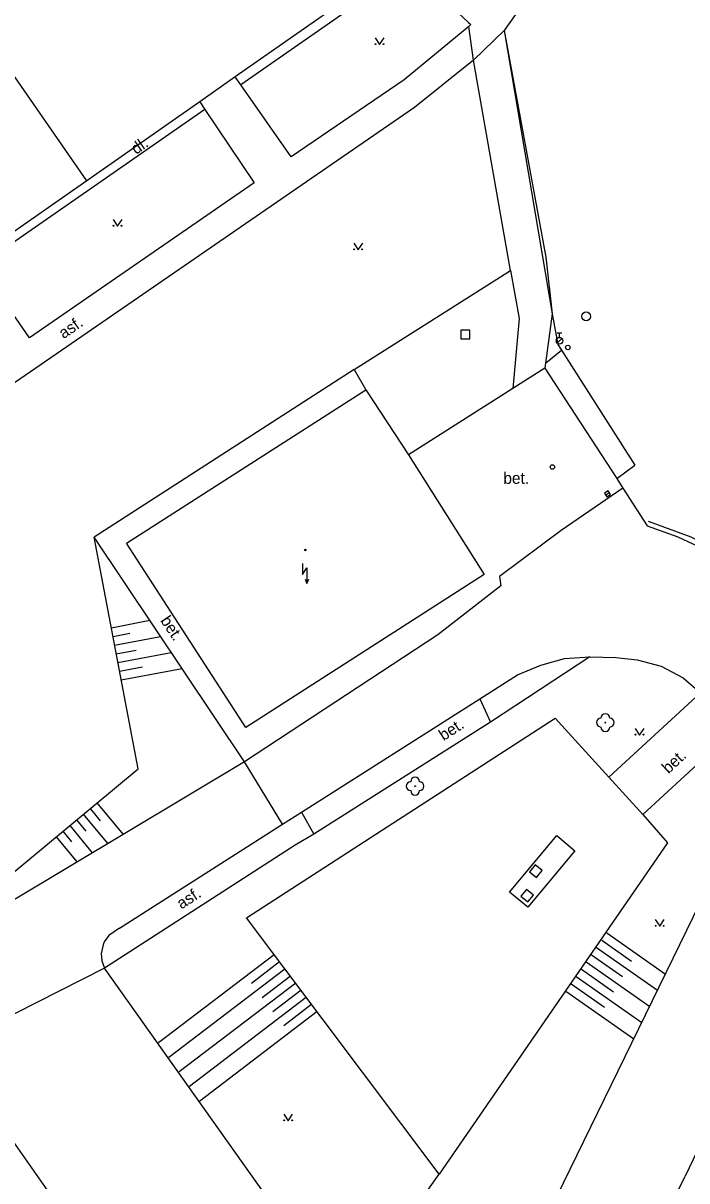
# Model space of a CAD drawing. Extents: x -602419 to -601554, y -1162937 to -1162362.
# Drawn here: x -601776.6 to -601739.3, y -1162613.9 to -1162548.7 of the extents above; entities that cross this region are included whole.
import ezdxf

# ---------------------------------------------------------------- set-up
doc = ezdxf.new("R2010")
doc.units = 0
doc.layers.add('Podklad', color=7, linetype='Continuous')

msp = doc.modelspace()

# ---------------------------------------------------------------- linework, layer by layer
at = {"layer": 'Podklad'}
for p, q in [((-601746.569, -1162566.726), (-601746.304, -1162566.461)), ((-601746.565, -1162566.1525), (-601746.315, -1162566.1525)), ((-601746.44, -1162566.4025), (-601746.44, -1162566.1525)), ((-601743.8432, -1162575.2806), (-601743.6368, -1162575.1394))]:
    msp.add_line(p, q, dxfattribs=at)
for points in [[(-601718.62, -1162386.7199), (-601719.1599, -1162386.65), (-601718.15, -1162413.82), (-601705.36, -1162413.11), (-601705.25, -1162448.94), (-601717.05, -1162449.02), (-601716.04, -1162480.32), (-601716.4099, -1162484.2199), (-601717.94, -1162489.4099), (-601746.45, -1162544.74), (-601749.56, -1162549.13)], [(-601770.89, -1162542.14), (-601771.19, -1162541.71), (-601764.49, -1162537.08), (-601757.42, -1162547.33), (-601764.39, -1162552.18)], [(-601763.49, -1162537.53), (-601751.5572, -1162548.6712), (-601751.43, -1162548.79)], [(-601758.14, -1162547.13), (-601764.7, -1162551.73)], [(-601773.05, -1162557.59), (-601779.59, -1162548.18)], [(-601751.43, -1162548.79), (-601751.5524, -1162548.8919), (-601755.18, -1162551.9099)], [(-601751.28, -1162550.79), (-601751.5524, -1162548.8919)], [(-601749.56, -1162549.13), (-601751.28, -1162550.79)], [(-601749.56, -1162549.13), (-601747.21, -1162561.88)], [(-601749.56, -1162549.13), (-601746.86, -1162565.07), (-601746.54, -1162566.7999), (-601746.33, -1162567.1299)], [(-601756.82, -1162549.545), (-601756.57, -1162549.92), (-601756.32, -1162549.545)], [(-601751.28, -1162550.79), (-601754.6, -1162553.46), (-601776.23, -1162568.34), (-601800.9, -1162585.3)], [(-601749.2, -1162562.63), (-601751.28, -1162550.79)], [(-601764.7, -1162551.73), (-601766.7, -1162553.14)], [(-601764.39, -1162552.18), (-601764.7, -1162551.73)], [(-601761.54, -1162556.23), (-601764.39, -1162552.18)], [(-601755.18, -1162551.9099), (-601761.54, -1162556.23)], [(-601766.4099, -1162553.58), (-601779.09, -1162562.38)], [(-601766.7, -1162553.14), (-601773.05, -1162557.59)], [(-601766.7, -1162553.14), (-601766.4099, -1162553.58)], [(-601766.4099, -1162553.58), (-601763.64, -1162557.71)], [(-601773.05, -1162557.59), (-601779.37, -1162561.98)], [(-601763.64, -1162557.71), (-601776.28, -1162566.42)], [(-601771.57, -1162559.765), (-601771.32, -1162560.14), (-601771.07, -1162559.765)], [(-601758.02, -1162561.0949), (-601757.77, -1162561.4699), (-601757.52, -1162561.0949)], [(-601747.21, -1162561.88), (-601746.86, -1162565.07), (-601747.2341, -1162567.8619), (-601747.27, -1162568.13)], [(-601776.28, -1162566.42), (-601779.09, -1162562.38)], [(-601758, -1162568.2199), (-601749.2, -1162562.63)], [(-601749.2, -1162562.63), (-601748.71, -1162565.34)], [(-601748.71, -1162565.34), (-601749.07, -1162569.28)], [(-601747.2341, -1162567.8619), (-601746.33, -1162567.1299)], [(-601746.33, -1162567.1299), (-601742.19, -1162573.5899)], [(-601758, -1162568.2199), (-601772.64, -1162577.65)], [(-601758, -1162568.2199), (-601757.34, -1162569.36)], [(-601747.27, -1162568.13), (-601749.07, -1162569.28)], [(-601747.27, -1162568.13), (-601743.2196, -1162574.3528), (-601742.87, -1162574.89)], [(-601770.82, -1162577.98), (-601757.34, -1162569.36)], [(-601757.34, -1162569.36), (-601754.94, -1162573.01)], [(-601749.07, -1162569.28), (-601754.94, -1162573.01)], [(-601754.94, -1162573.01), (-601750.68, -1162579.76)], [(-601743.2196, -1162574.3528), (-601742.19, -1162573.5899)], [(-601742.87, -1162574.89), (-601746.35, -1162577.28), (-601749.81, -1162579.86), (-601749.75, -1162580.4), (-601753.3, -1162583.15), (-601764.18, -1162590.3)], [(-601742.87, -1162574.89), (-601741.51, -1162577.02)], [(-601741.51, -1162577.02), (-601739.78, -1162577.63), (-601738.13, -1162578.4099), (-601736.53, -1162579.31), (-601735.04, -1162580.38), (-601734.59, -1162580.77), (-601733.65, -1162581.57), (-601732.37, -1162582.89), (-601731.21, -1162584.3), (-601730.33, -1162585.59), (-601729.7, -1162586.6599), (-601729.34, -1162587.84), (-601729.1, -1162589.32), (-601729.05, -1162590.81), (-601729.2, -1162591.99), (-601729.4, -1162592.88)], [(-601734.42, -1162580.5), (-601735.99, -1162579.35), (-601737.31, -1162578.52), (-601739.02, -1162577.65), (-601741.43, -1162576.76)], [(-601783.94, -1162602.12), (-601770.17, -1162590.69), (-601772.64, -1162577.65)], [(-601764.18, -1162590.3), (-601772.64, -1162577.65)], [(-601764.11, -1162588.36), (-601770.82, -1162577.98)], [(-601760.9099, -1162579.13), (-601760.9099, -1162579.755), (-601760.6599, -1162579.38), (-601760.6599, -1162580.255)], [(-601750.68, -1162579.76), (-601764.11, -1162588.36)], [(-601760.7694, -1162580.0105), (-601760.6599, -1162580.255), (-601760.5504, -1162580.0105)], [(-601771.67, -1162582.75), (-601769.51, -1162582.33)], [(-601771.58, -1162583.24), (-601770.63, -1162583.06)], [(-601771.49, -1162583.73), (-601768.9, -1162583.24)], [(-601771.4, -1162584.2199), (-601770.28, -1162584.01)], [(-601771.3, -1162584.71), (-601768.3, -1162584.14)], [(-601771.21, -1162585.2), (-601769.92, -1162584.96)], [(-601744.74, -1162584.39), (-601750.33, -1162588.06)], [(-601748.8, -1162585.4), (-601747.5, -1162584.86), (-601746.15, -1162584.48), (-601744.74, -1162584.39), (-601743.26, -1162584.42), (-601742.07, -1162584.56), (-601740.71, -1162584.9099), (-601739.48, -1162585.58), (-601738.5, -1162586.42)], [(-601771.12, -1162585.69), (-601767.69, -1162585.05)], [(-601750.93, -1162586.76), (-601748.8, -1162585.4)], [(-601760.96, -1162593.13), (-601750.93, -1162586.76)], [(-601750.93, -1162586.76), (-601750.33, -1162588.06), (-601760.28, -1162594.38)], [(-601738.5, -1162586.42), (-601743.6599, -1162591.1599)], [(-601741.74, -1162593.26), (-601740.35, -1162594.86), (-601753.21, -1162613.52), (-601764.07, -1162599.08), (-601746.68, -1162587.85), (-601743.6599, -1162591.1599)], [(-601742.18, -1162588.415), (-601741.93, -1162588.79), (-601741.68, -1162588.415)], [(-601741.74, -1162593.26), (-601737.02, -1162588.92)], [(-601764.18, -1162590.3), (-601783.94, -1162602.12)], [(-601762.0407, -1162593.8189), (-601764.18, -1162590.3)], [(-601743.6599, -1162591.1599), (-601741.74, -1162593.26)], [(-601772.49, -1162592.61), (-601771.01, -1162594.39)], [(-601773.26, -1162593.25), (-601771.88, -1162594.9099)], [(-601772.87, -1162592.93), (-601772.3, -1162593.62)], [(-601771.2199, -1162599.67), (-601762.0407, -1162593.8189), (-601760.96, -1162593.13)], [(-601760.96, -1162593.13), (-601760.28, -1162594.38)], [(-601729.4, -1162592.88), (-601739.36, -1162613.62)], [(-601774.02, -1162593.89), (-601772.75, -1162595.43)], [(-601773.64, -1162593.57), (-601773.11, -1162594.21)], [(-601774.79, -1162594.53), (-601773.62, -1162595.94)], [(-601774.4099, -1162594.21), (-601773.92, -1162594.8)], [(-601760.28, -1162594.38), (-601761.32, -1162595)], [(-601749.25, -1162597.64), (-601746.59, -1162594.44), (-601745.58, -1162595.31), (-601748.23, -1162598.49), (-601749.25, -1162597.64)], [(-601761.32, -1162595), (-601772.06, -1162601.92)], [(-601811.44, -1162699.63), (-601790.2, -1162676.34), (-601776.01, -1162658.53), (-601771.0161, -1162652.0886), (-601765.466, -1162644.9297), (-601762.9, -1162641.62), (-601760.5218, -1162637.8699), (-601758.93, -1162635.36), (-601755.8662, -1162630.788), (-601750.48, -1162622.75), (-601746.602, -1162614.8054), (-601737.73, -1162596.63)], [(-601741.05, -1162599.185), (-601740.8, -1162599.56), (-601740.55, -1162599.185)], [(-601771.2199, -1162599.67), (-601771.81, -1162600.08), (-601772.07, -1162600.44), (-601772.14, -1162600.61), (-601772.25, -1162601.09), (-601772.21, -1162601.51), (-601772.06, -1162601.92)], [(-601743.78, -1162599.93), (-601740.48, -1162602.25)], [(-601744.06, -1162600.34), (-601742.38, -1162601.52)], [(-601762.5, -1162601.17), (-601769.01, -1162606.13)], [(-601744.64, -1162601.1599), (-601742.89, -1162602.39)], [(-601744.35, -1162600.75), (-601740.92, -1162603.1599)], [(-601772.06, -1162601.92), (-601780.9099, -1162606.4099)], [(-601767.78, -1162628.02), (-601762.44, -1162624.15), (-601759.94, -1162619), (-601772.06, -1162601.92)], [(-601762.2, -1162601.57), (-601763.79, -1162602.78)], [(-601744.93, -1162601.57), (-601741.36, -1162604.07)], [(-601761.9, -1162601.9699), (-601768.43, -1162606.95)], [(-601761.59, -1162602.36), (-601763.18, -1162603.58)], [(-601745.5, -1162602.39), (-601741.81, -1162604.98)], [(-601745.21, -1162601.98), (-601743.4, -1162603.25)], [(-601761.29, -1162602.76), (-601767.86, -1162607.76)], [(-601760.99, -1162603.1599), (-601762.58, -1162604.37)], [(-601746.08, -1162603.21), (-601742.25, -1162605.89)], [(-601745.79, -1162602.8), (-601743.9099, -1162604.12)], [(-601760.68, -1162603.56), (-601767.28, -1162608.58)], [(-601760.08, -1162604.35), (-601766.7, -1162609.4)], [(-601760.38, -1162603.95), (-601761.9699, -1162605.17)], [(-601780.9099, -1162606.4099), (-601769.99, -1162621.98), (-601771.4, -1162622.88)], [(-601761.9699, -1162610.135), (-601761.7199, -1162610.51), (-601761.4699, -1162610.135)], [(-601803.88, -1162705.94), (-601782.56, -1162681.86), (-601769.7, -1162666.09), (-601758, -1162650.59), (-601755.1, -1162646.75), (-601750.51, -1162639.84), (-601749.54, -1162638.24), (-601749.69, -1162638.14), (-601750.71, -1162637.46), (-601745.19, -1162625.47), (-601739.36, -1162613.62)], [(-601761.56, -1162624.8199), (-601755.72, -1162617.0199), (-601753.21, -1162613.52)]]:
    msp.add_lwpolyline(points, dxfattribs=at)
for points in [[(-601751.99, -1162566.49), (-601751.49, -1162566.49), (-601751.49, -1162565.99), (-601751.99, -1162565.99)], [(-601743.7726, -1162575.3837), (-601743.5663, -1162575.2426), (-601743.7074, -1162575.0363), (-601743.9137, -1162575.1774)], [(-601748.1221, -1162596.4917), (-601747.7383, -1162596.8121), (-601747.4179, -1162596.4283), (-601747.8017, -1162596.1079)], [(-601748.6122, -1162597.871), (-601748.229, -1162598.1922), (-601747.9078, -1162597.809), (-601748.291, -1162597.4878)]]:
    msp.add_lwpolyline(points, close=True, dxfattribs=at)
for centre, radius in [((-601756.7951, -1162549.8949), 0.025), ((-601756.3454, -1162549.8949), 0.025), ((-601771.5451, -1162560.1149), 0.025), ((-601771.0954, -1162560.1149), 0.025), ((-601757.9951, -1162561.4448), 0.025), ((-601757.5454, -1162561.4448), 0.025), ((-601744.94, -1162565.2199), 0.25), ((-601746.44, -1162566.59), 0.1875), ((-601745.9699, -1162566.9699), 0.125), ((-601746.84, -1162573.7), 0.125), ((-601760.75, -1162578.37), 0.045), ((-601760.75, -1162578.37), 0.0199), ((-601743.86, -1162588.09), 0.025), ((-601742.1551, -1162588.7649), 0.025), ((-601741.7054, -1162588.7649), 0.025), ((-601754.57, -1162591.67), 0.025), ((-601741.0251, -1162599.5349), 0.025), ((-601740.5754, -1162599.5349), 0.025), ((-601761.945, -1162610.4849), 0.025), ((-601761.4953, -1162610.4849), 0.025)]:
    msp.add_circle(centre, radius, dxfattribs=at)
for centre, start, end in [((-601743.86, -1162587.84), 0, 180), ((-601744.11, -1162588.09), 90, 270), ((-601743.61, -1162588.09), 270, 90), ((-601743.86, -1162588.34), 180, 0), ((-601754.82, -1162591.67), 90, 270), ((-601754.57, -1162591.42), 0, 180), ((-601754.32, -1162591.67), 270, 90), ((-601754.57, -1162591.92), 180, 0)]:
    msp.add_arc(centre, 0.25, start, end, dxfattribs=at)

# ---------------------------------------------------------------- texts
for s, rotation, p in [('dl.', 34.79, (-601770.28, -1162556.13)), ('asf.', 34.53, (-601774.36, -1162566.51)), ('bet.', 303.77, (-601768.94, -1162582.35)), ('bet.', 32.74, (-601752.9699, -1162589.14)), ('bet.', 42.64, (-601740.31, -1162591)), ('asf.', 32.74, (-601767.73, -1162598.62))]:
    msp.add_text(s, height=0.65, rotation=rotation, dxfattribs=at).set_placement(p)
msp.add_text('bet.', height=0.65, dxfattribs=at).set_placement((-601749.6, -1162574.65))

doc.saveas('drawing.dxf')
